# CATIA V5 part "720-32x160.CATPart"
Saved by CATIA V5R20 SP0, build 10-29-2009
Part number: 720-32x160
Definition: NONE
Nomenclature: 720-32x160
Source: Unknown
Description: 720-32x160
Bounding box of the stored display mesh (mm): x 0 to 160, y -16 to 16, z -16 to 16
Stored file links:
  C:\Users\Utente\Desktop\IO LAVORO\3D X SITO CF\X SITO\720\720-32x160.CATPart

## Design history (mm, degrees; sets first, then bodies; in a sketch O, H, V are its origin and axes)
Body1 "720-32x160" (main body)
  Solid1: solid without history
